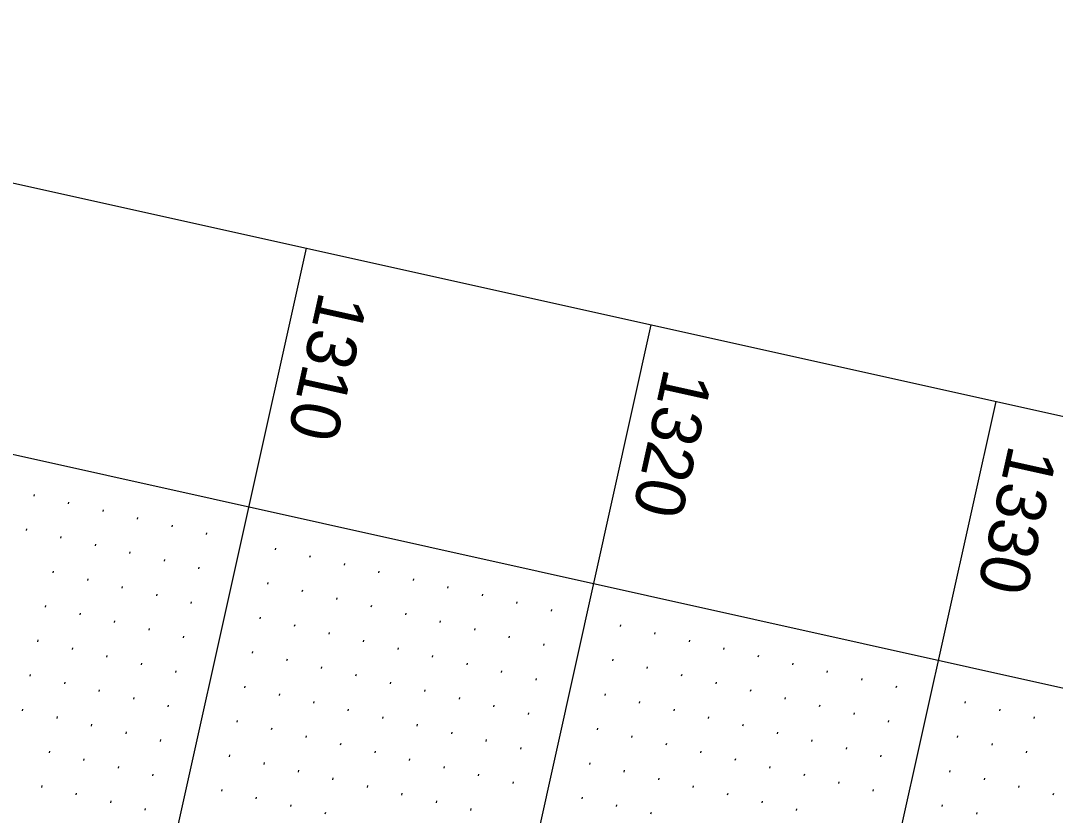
# Model space of a CAD drawing. Extents: x 2149268 to 2150830, y 142155 to 144285.
# Drawn here: x 2149971.3 to 2150117.7, y 143829.8 to 143942.3 of the extents above; entities that cross this region are included whole.
import ezdxf

# ---------------------------------------------------------------- set-up
doc = ezdxf.new("R2010")
doc.units = 0
for name, color, linetype in [('SHT_Plan_Profile_Sheet_Elev_Txt', 7, 'Continuous'), ('SHT_Profile_Grid_Major', 7, 'Continuous'), ('SHT_Profile_Grid_Minor', 7, 'Continuous'), ('SHT_Sheet_Border', 7, 'Continuous')]:
    doc.layers.add(name, color=color, linetype=linetype)

msp = doc.modelspace()

# ---------------------------------------------------------------- linework, layer by layer
at = {"layer": 'SHT_Profile_Grid_Major'}
for p, q in [((2150011.64, 143910.11), (2149669.77, 142372.66)), ((2150060.45, 143899.25), (2149718.58, 142361.8)), ((2150109.25, 143888.4), (2149767.39, 142350.95))]:
    msp.add_line(p, q, dxfattribs=at)
at = {"layer": 'SHT_Profile_Grid_Minor'}
for p, q in [((2149973.16, 143875.25), (2149973.1, 143875.01)), ((2149978.04, 143874.17), (2149977.98, 143873.92)), ((2149982.92, 143873.08), (2149982.86, 143872.84)), ((2149987.8, 143872), (2149987.74, 143871.75)), ((2149972.07, 143870.37), (2149972.02, 143870.13)), ((2149992.68, 143870.91), (2149992.62, 143870.67)), ((2149976.95, 143869.29), (2149976.9, 143869.04)), ((2149997.56, 143869.83), (2149997.51, 143869.58)), ((2149981.83, 143868.2), (2149981.78, 143867.96)), ((2150007.32, 143867.66), (2150007.27, 143867.41)), ((2149986.71, 143867.12), (2149986.66, 143866.87)), ((2149991.59, 143866.03), (2149991.54, 143865.79)), ((2150012.2, 143866.57), (2150012.15, 143866.33)), ((2149975.87, 143864.41), (2149975.81, 143864.16)), ((2149996.47, 143864.95), (2149996.42, 143864.7)), ((2150017.08, 143865.49), (2150017.03, 143865.24)), ((2150021.96, 143864.4), (2150021.91, 143864.16)), ((2149980.75, 143863.32), (2149980.69, 143863.08)), ((2150026.84, 143863.32), (2150026.79, 143863.07)), ((2149985.63, 143862.24), (2149985.57, 143861.99)), ((2150006.24, 143862.78), (2150006.18, 143862.53)), ((2150011.12, 143861.69), (2150011.06, 143861.45)), ((2150031.72, 143862.23), (2150031.67, 143861.99)), ((2149990.51, 143861.15), (2149990.45, 143860.91)), ((2149995.39, 143860.07), (2149995.33, 143859.82)), ((2150016, 143860.61), (2150015.94, 143860.36)), ((2150036.61, 143861.15), (2150036.55, 143860.9)), ((2150041.49, 143860.06), (2150041.43, 143859.82)), ((2149974.78, 143859.53), (2149974.73, 143859.28)), ((2150020.88, 143859.52), (2150020.82, 143859.28)), ((2150046.37, 143858.97), (2150046.31, 143858.73)), ((2149979.66, 143858.44), (2149979.61, 143858.2)), ((2149984.54, 143857.36), (2149984.49, 143857.11)), ((2150005.15, 143857.9), (2150005.1, 143857.65)), ((2150025.76, 143858.43), (2150025.7, 143858.19)), ((2150030.64, 143857.35), (2150030.59, 143857.11)), ((2149989.42, 143856.27), (2149989.37, 143856.03)), ((2150010.03, 143856.81), (2150009.98, 143856.57)), ((2150014.91, 143855.72), (2150014.86, 143855.48)), ((2150035.52, 143856.26), (2150035.47, 143856.02)), ((2150056.13, 143856.8), (2150056.07, 143856.56)), ((2150061.01, 143855.72), (2150060.96, 143855.47)), ((2149973.7, 143854.65), (2149973.64, 143854.4)), ((2149994.3, 143855.18), (2149994.25, 143854.94)), ((2150019.79, 143854.64), (2150019.74, 143854.4)), ((2150040.4, 143855.18), (2150040.35, 143854.93)), ((2150065.89, 143854.63), (2150065.84, 143854.39)), ((2149978.58, 143853.56), (2149978.52, 143853.32)), ((2150004.07, 143853.01), (2150004.01, 143852.77)), ((2150024.67, 143853.55), (2150024.62, 143853.31)), ((2150045.28, 143854.09), (2150045.23, 143853.85)), ((2150070.77, 143853.55), (2150070.72, 143853.3)), ((2149983.46, 143852.47), (2149983.4, 143852.23)), ((2149988.34, 143851.39), (2149988.28, 143851.15)), ((2150008.95, 143851.93), (2150008.89, 143851.69)), ((2150029.55, 143852.47), (2150029.5, 143852.22)), ((2150034.44, 143851.38), (2150034.38, 143851.14)), ((2150055.04, 143851.92), (2150054.99, 143851.68)), ((2150075.65, 143852.46), (2150075.6, 143852.22)), ((2150080.53, 143851.38), (2150080.48, 143851.13)), ((2149972.61, 143849.76), (2149972.56, 143849.52)), ((2149993.22, 143850.3), (2149993.16, 143850.06)), ((2150013.83, 143850.84), (2150013.77, 143850.6)), ((2150018.71, 143849.76), (2150018.65, 143849.51)), ((2150039.32, 143850.3), (2150039.26, 143850.05)), ((2150059.92, 143850.84), (2150059.87, 143850.59)), ((2150064.81, 143849.75), (2150064.75, 143849.51)), ((2150085.41, 143850.29), (2150085.36, 143850.05)), ((2149977.49, 143848.68), (2149977.44, 143848.44)), ((2150023.59, 143848.67), (2150023.53, 143848.43)), ((2150044.2, 143849.21), (2150044.14, 143848.97)), ((2150069.69, 143848.67), (2150069.63, 143848.42)), ((2150090.29, 143849.21), (2150090.24, 143848.96)), ((2149982.37, 143847.59), (2149982.32, 143847.35)), ((2150002.98, 143848.13), (2150002.93, 143847.89)), ((2150007.86, 143847.05), (2150007.81, 143846.8)), ((2150028.47, 143847.59), (2150028.41, 143847.34)), ((2150053.96, 143847.04), (2150053.9, 143846.8)), ((2150074.57, 143847.58), (2150074.51, 143847.34)), ((2150095.18, 143848.12), (2150095.12, 143847.88)), ((2149987.25, 143846.51), (2149987.2, 143846.26)), ((2149992.13, 143845.42), (2149992.08, 143845.18)), ((2150012.74, 143845.96), (2150012.69, 143845.72)), ((2150033.35, 143846.5), (2150033.3, 143846.26)), ((2150038.23, 143845.42), (2150038.18, 143845.17)), ((2150058.84, 143845.96), (2150058.78, 143845.71)), ((2150079.45, 143846.5), (2150079.39, 143846.25)), ((2150084.33, 143845.41), (2150084.27, 143845.17)), ((2150104.94, 143845.95), (2150104.88, 143845.71)), ((2149971.52, 143844.88), (2149971.47, 143844.64)), ((2150017.62, 143844.88), (2150017.57, 143844.63)), ((2150043.11, 143844.33), (2150043.06, 143844.09)), ((2150063.72, 143844.87), (2150063.67, 143844.63)), ((2150089.21, 143844.33), (2150089.15, 143844.08)), ((2150109.82, 143844.87), (2150109.76, 143844.62)), ((2149976.41, 143843.8), (2149976.35, 143843.55)), ((2149981.29, 143842.71), (2149981.23, 143842.47)), ((2150001.89, 143843.25), (2150001.84, 143843.01)), ((2150022.5, 143843.79), (2150022.45, 143843.55)), ((2150027.38, 143842.71), (2150027.33, 143842.46)), ((2150068.6, 143843.79), (2150068.55, 143843.54)), ((2150073.48, 143842.7), (2150073.43, 143842.46)), ((2150094.09, 143843.24), (2150094.04, 143843)), ((2150114.7, 143843.78), (2150114.64, 143843.54)), ((2149986.17, 143841.63), (2149986.11, 143841.38)), ((2150006.78, 143842.17), (2150006.72, 143841.92)), ((2150011.66, 143841.08), (2150011.6, 143840.84)), ((2150032.26, 143841.62), (2150032.21, 143841.38)), ((2150052.87, 143842.16), (2150052.82, 143841.92)), ((2150057.75, 143841.08), (2150057.7, 143840.83)), ((2150078.36, 143841.62), (2150078.31, 143841.37)), ((2150103.85, 143841.07), (2150103.8, 143840.83)), ((2149991.05, 143840.54), (2149990.99, 143840.3)), ((2150016.54, 143840), (2150016.48, 143839.75)), ((2150037.15, 143840.54), (2150037.09, 143840.29)), ((2150062.63, 143839.99), (2150062.58, 143839.75)), ((2150083.24, 143840.53), (2150083.19, 143840.29)), ((2150108.73, 143839.99), (2150108.68, 143839.74)), ((2149975.32, 143838.92), (2149975.27, 143838.67)), ((2150000.81, 143838.37), (2150000.76, 143838.13)), ((2150021.42, 143838.91), (2150021.36, 143838.67)), ((2150042.03, 143839.45), (2150041.97, 143839.21)), ((2150067.52, 143838.91), (2150067.46, 143838.66)), ((2150088.12, 143839.45), (2150088.07, 143839.2)), ((2150093, 143838.36), (2150092.95, 143838.12)), ((2150113.61, 143838.9), (2150113.56, 143838.66)), ((2149980.2, 143837.83), (2149980.15, 143837.59)), ((2149985.08, 143836.75), (2149985.03, 143836.5)), ((2150005.69, 143837.29), (2150005.64, 143837.04)), ((2150026.3, 143837.83), (2150026.24, 143837.58)), ((2150031.18, 143836.74), (2150031.13, 143836.5)), ((2150051.79, 143837.28), (2150051.73, 143837.04)), ((2150072.4, 143837.82), (2150072.34, 143837.58)), ((2150077.28, 143836.74), (2150077.22, 143836.49)), ((2149989.96, 143835.66), (2149989.91, 143835.42)), ((2150010.57, 143836.2), (2150010.52, 143835.96)), ((2150015.45, 143835.12), (2150015.4, 143834.87)), ((2150036.06, 143835.66), (2150036.01, 143835.41)), ((2150056.67, 143836.2), (2150056.61, 143835.95)), ((2150061.55, 143835.11), (2150061.5, 143834.87)), ((2150082.16, 143835.65), (2150082.1, 143835.41)), ((2150102.77, 143836.19), (2150102.71, 143835.95)), ((2150107.65, 143835.1), (2150107.59, 143834.86)), ((2149974.23, 143834.04), (2149974.18, 143833.79)), ((2150020.33, 143834.03), (2150020.28, 143833.79)), ((2150040.94, 143834.57), (2150040.89, 143834.33)), ((2150066.43, 143834.02), (2150066.38, 143833.78)), ((2150087.04, 143834.56), (2150086.98, 143834.32)), ((2150112.53, 143834.02), (2150112.47, 143833.77)), ((2149979.12, 143832.95), (2149979.06, 143832.71)), ((2149999.72, 143833.49), (2149999.67, 143833.25)), ((2150004.6, 143832.41), (2150004.55, 143832.16)), ((2150025.21, 143832.95), (2150025.16, 143832.7)), ((2150050.7, 143832.4), (2150050.65, 143832.16)), ((2150071.31, 143832.94), (2150071.26, 143832.7)), ((2150091.92, 143833.48), (2150091.87, 143833.24)), ((2150117.41, 143832.93), (2150117.35, 143832.69)), ((2149984, 143831.87), (2149983.94, 143831.62)), ((2149988.88, 143830.78), (2149988.82, 143830.54)), ((2150009.49, 143831.32), (2150009.43, 143831.08)), ((2150030.09, 143831.86), (2150030.04, 143831.62)), ((2150034.97, 143830.78), (2150034.92, 143830.53)), ((2150055.58, 143831.31), (2150055.53, 143831.07)), ((2150076.19, 143831.85), (2150076.14, 143831.61)), ((2150081.07, 143830.77), (2150081.02, 143830.53)), ((2150101.68, 143831.31), (2150101.63, 143831.06)), ((2150014.37, 143830.24), (2150014.31, 143829.99)), ((2150060.46, 143830.23), (2150060.41, 143829.99)), ((2150106.56, 143830.22), (2150106.51, 143829.98))]:
    msp.add_line(p, q, dxfattribs=at)
at = {"layer": 'SHT_Sheet_Border'}
msp.add_line((2149710.65, 143938.62), (2150198.73, 143830.09), dxfattribs=at)
msp.add_lwpolyline([(2150726.67, 143751.11), (2150384.81, 142213.66), (2149359.84, 142441.57), (2149701.71, 143979.02)], close=True, dxfattribs=at)

# ---------------------------------------------------------------- texts
at = {"layer": 'SHT_Plan_Profile_Sheet_Elev_Txt'}
for s, p in [('1310', (2150013.55, 143904.16)), ('1320', (2150062.36, 143893.3)), ('1330', (2150111.16, 143882.45))]:
    msp.add_text(s, height=7, rotation=257.4638, dxfattribs=at).set_placement(p)

doc.saveas('drawing.dxf')
